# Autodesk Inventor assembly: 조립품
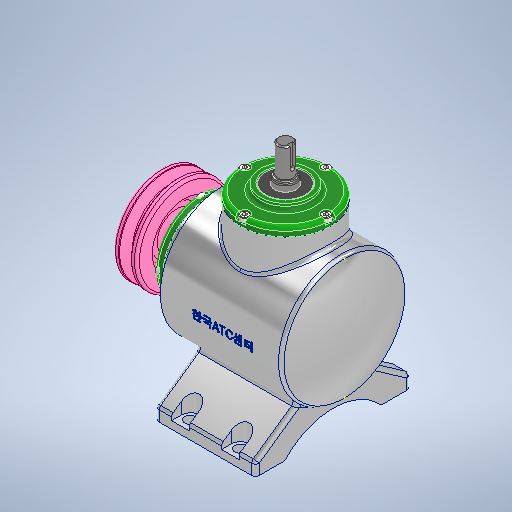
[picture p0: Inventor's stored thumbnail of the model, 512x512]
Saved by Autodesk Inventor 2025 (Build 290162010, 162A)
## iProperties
Created: 2024-07
Part Number: 조립품
Document SubType Name: Assembly
Designer: Admin
Author: Admin
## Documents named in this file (15)
- C:\Users\Admin\Desktop\740709V1002\조립품.iam
- C:\Users\Admin\Desktop\740709V1002\본체.ipt
- C:\Users\Admin\Desktop\740709V1002\V-벨트풀리\V-벨트풀리.ipt
- C:\Users\Admin\Desktop\740709V1002\메인 베벨기어\메인 베벨기어.ipt
- C:\Users\Admin\Desktop\740709V1002\메인 축\메인 축.ipt
- C:\Users\Admin\Desktop\740709V1002\베어링 6203\베어링 6203.ipt
- C:\Users\Admin\Desktop\740709V1002\볼트 M4 x 10\볼트 M4 x 10.ipt
- C:\Users\Admin\Desktop\740709V1002\서브 베벨기어\서브 베벨기어.ipt
- C:\Users\Admin\Desktop\740709V1002\서브 축\서브 축.ipt
- C:\Users\Admin\Desktop\740709V1002\오일실 17 x 32 x 8\오일실 17 x 32 x 8.ipt
- C:\Users\Admin\Desktop\740709V1002\와셔 4 x 16\와셔 4 x 16.ipt
- C:\Users\Admin\Desktop\740709V1002\육각볼트 M4 x 8\육각볼트 M4 x 8.ipt
- C:\Users\Admin\Desktop\740709V1002\커버\커버.ipt
- C:\Users\Admin\Desktop\740709V1002\키 4 x 4 x 14\키 4 x 4 x 14.ipt
- C:\Users\Admin\Desktop\740709V1002\키 5 x 5 x 14\키 5 x 5 x 14.ipt
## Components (1 placed, 1 different names)
1. V-벨트풀리:1 — 각도:5
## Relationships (1: Angle 1)
- 각도:5 [Angle]: V-벨트풀리:1
